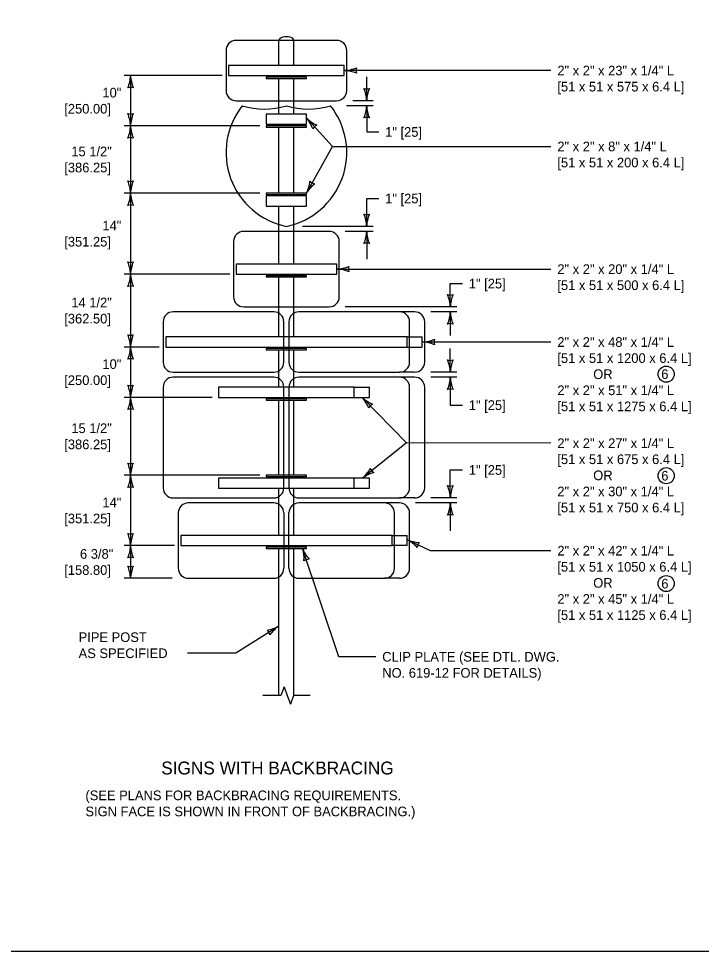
# Model space of a CAD drawing. Extents: x 49991.4 to 50021, y 49987.6 to 50011.4.
# Drawn here: x 50002.88 to 50007.12, y 49987.8 to 49993.6 of the extents above; entities that cross this region are included whole.
import ezdxf

# ---------------------------------------------------------------- set-up
doc = ezdxf.new("R2010")
doc.units = 0
for name, color, linetype in [('Level 1', 7, 'Continuous'), ('Level 2', 7, 'Continuous'), ('Level 3', 7, 'Continuous'), ('Level 4', 7, 'Continuous'), ('Level 6', 7, 'Continuous')]:
    doc.layers.add(name, color=color, linetype=linetype)

msp = doc.modelspace()

# ---------------------------------------------------------------- linework, layer by layer
at = {"layer": 'Level 1'}
for p, q in [((50004.4975, 49993.3041), (50004.4975, 49993.4604)), ((50004.5913, 49993.3041), (50004.5913, 49993.4604)), ((50004.4975, 49993.0013), (50004.4975, 49993.2241)), ((50004.5913, 49993.0013), (50004.5913, 49993.2241)), ((50004.4975, 49992.5108), (50004.4975, 49992.9213)), ((50004.5913, 49992.5108), (50004.5913, 49992.9213)), ((50004.4975, 49992.07), (50004.4975, 49992.4308)), ((50004.5913, 49992.07), (50004.5913, 49992.4308)), ((50004.4975, 49991.617), (50004.4975, 49991.99)), ((50004.5913, 49991.617), (50004.5913, 49991.99)), ((50005.2948, 49991.617), (50003.7948, 49991.617)), ((50003.7948, 49991.617), (50003.7948, 49991.5545)), ((50005.2948, 49991.5545), (50005.2948, 49991.617)), ((50003.7948, 49991.5545), (50005.2948, 49991.5545)), ((50004.4975, 49991.3041), (50004.4975, 49991.537)), ((50004.5132, 49991.5545), (50004.6292, 49991.5545)), ((50004.5913, 49991.3041), (50004.5913, 49991.537)), ((50004.9667, 49991.3041), (50004.1229, 49991.3041)), ((50004.1229, 49991.3041), (50004.1229, 49991.2416)), ((50004.9667, 49991.2416), (50004.9667, 49991.3041)), ((50004.1229, 49991.2416), (50004.9667, 49991.2416)), ((50004.4975, 49990.7576), (50004.4975, 49991.2241)), ((50004.5913, 49990.7576), (50004.5913, 49991.2241)), ((50004.9667, 49990.7401), (50004.1229, 49990.7401)), ((50004.1229, 49990.7401), (50004.1229, 49990.6776)), ((50004.9667, 49990.6776), (50004.9667, 49990.7401)), ((50004.1229, 49990.6776), (50004.9667, 49990.6776)), ((50004.4975, 49990.3826), (50004.4975, 49990.6776)), ((50004.5913, 49990.3826), (50004.5913, 49990.6776)), ((50005.2011, 49990.3826), (50003.8886, 49990.3826)), ((50003.8886, 49990.3826), (50003.8886, 49990.3201)), ((50005.2011, 49990.3201), (50005.2011, 49990.3826)), ((50003.8886, 49990.3201), (50005.2011, 49990.3201)), ((50004.4975, 49989.3888), (50004.4975, 49990.3026)), ((50004.5913, 49989.3888), (50004.5913, 49990.3026))]:
    msp.add_line(p, q, dxfattribs=at)
for points in [[(49999.3835, 49998.9992), (50016.7501, 49998.9992), (50016.7501, 49987.7988), (49999.3835, 49987.7988)], [(50004.1851, 49993.2416), (50004.9038, 49993.2416), (50004.9038, 49993.3041), (50004.1851, 49993.3041)], [(50004.4194, 49993.2241), (50004.6694, 49993.2241), (50004.6694, 49993.2319), (50004.4194, 49993.2319)], [(50004.4198, 49992.9388), (50004.6698, 49992.9388), (50004.6698, 49993.0013), (50004.4198, 49993.0013)], [(50004.4198, 49992.9213), (50004.6698, 49992.9213), (50004.6698, 49992.9291), (50004.4198, 49992.9291)], [(50004.4198, 49992.503), (50004.6698, 49992.503), (50004.6698, 49992.5108), (50004.4198, 49992.5108)], [(50004.4198, 49992.4308), (50004.6698, 49992.4308), (50004.6698, 49992.4933), (50004.4198, 49992.4933)], [(50004.2323, 49992.0075), (50004.8573, 49992.0075), (50004.8573, 49992.07), (50004.2323, 49992.07)], [(50004.4198, 49991.99), (50004.6698, 49991.99), (50004.6698, 49991.9978), (50004.4198, 49991.9978)], [(50004.4198, 49991.537), (50004.6698, 49991.537), (50004.6698, 49991.5448), (50004.4198, 49991.5448)], [(50004.4198, 49991.2241), (50004.6698, 49991.2241), (50004.6698, 49991.2319), (50004.4198, 49991.2319)], [(50004.4198, 49990.7498), (50004.6698, 49990.7498), (50004.6698, 49990.7576), (50004.4198, 49990.7576)], [(50004.4198, 49990.3026), (50004.6698, 49990.3026), (50004.6698, 49990.3104), (50004.4198, 49990.3104)]]:
    msp.add_lwpolyline(points, close=True, dxfattribs=at)
msp.add_ellipse((50004.5444, 49993.4604), major_axis=(0.0469, 0), ratio=0.488273, start_param=0, end_param=3.141593, dxfattribs=at)
at = {"layer": 'Level 2'}
for centre in [(50006.9044, 49991.386), (50006.9044, 49990.7548), (50006.9044, 49990.0842)]:
    msp.add_circle(centre, 0.05, dxfattribs=at)
at = {"layer": 'Level 3'}
for p, q in [((50006.1882, 49993.2729), (50004.9038, 49993.2729)), ((50004.1451, 49993.2416), (50003.5361, 49993.2416)), ((50003.5761, 49993.2416), (50003.5761, 49992.9291)), ((50005.0434, 49993.0854), (50005.0434, 49993.2329)), ((50005.0834, 49993.0854), (50004.9569, 49993.0854)), ((50005.0834, 49993.0543), (50004.9184, 49993.0543)), ((50005.0434, 49993.0542), (50005.0434, 49992.8911)), ((50004.6698, 49992.9782), (50004.8302, 49992.8011)), ((50004.3798, 49992.9291), (50003.5361, 49992.9291)), ((50003.5761, 49992.9291), (50003.5761, 49992.5108)), ((50005.0434, 49992.8911), (50005.1184, 49992.8911)), ((50004.6689, 49992.5108), (50004.8302, 49992.8011)), ((50004.8302, 49992.8011), (50006.1882, 49992.8011)), ((50004.3798, 49992.5108), (50003.5361, 49992.5108)), ((50003.5761, 49992.5108), (50003.5761, 49992.0075)), ((50005.0434, 49992.3043), (50005.0434, 49992.4778)), ((50005.0434, 49992.4778), (50005.1184, 49992.4778)), ((50005.0834, 49992.3043), (50004.6447, 49992.3043)), ((50005.0834, 49992.2731), (50004.9104, 49992.2731)), ((50005.0434, 49992.2731), (50005.0434, 49992.0997)), ((50004.8573, 49992.0387), (50006.1882, 49992.0387)), ((50004.1923, 49992.0075), (50003.5361, 49992.0075)), ((50003.5761, 49992.0075), (50003.5761, 49991.5545)), ((50005.563, 49991.8044), (50005.563, 49991.9487)), ((50005.563, 49991.9487), (50005.638, 49991.9487)), ((50005.603, 49991.8044), (50004.9104, 49991.8044)), ((50005.603, 49991.7732), (50005.4414, 49991.7732)), ((50005.563, 49991.7732), (50005.563, 49991.6257)), ((50006.1882, 49991.5857), (50005.3886, 49991.5857)), ((50003.7548, 49991.5545), (50003.5361, 49991.5545)), ((50003.5761, 49991.5545), (50003.5761, 49991.2416)), ((50005.563, 49991.3982), (50005.563, 49991.5457)), ((50005.603, 49991.3982), (50005.4414, 49991.3982)), ((50005.603, 49991.367), (50005.4414, 49991.367)), ((50005.563, 49991.367), (50005.563, 49991.1936)), ((50004.0829, 49991.2416), (50003.5361, 49991.2416)), ((50003.5761, 49991.2416), (50003.5761, 49990.7576)), ((50005.2913, 49990.9584), (50005.0148, 49991.2416)), ((50005.563, 49991.1936), (50005.638, 49991.1936)), ((50005.2913, 49990.9584), (50005.0171, 49990.7401)), ((50006.1882, 49990.957), (50005.2913, 49990.9584)), ((50004.3798, 49990.7576), (50003.5361, 49990.7576)), ((50003.5761, 49990.7576), (50003.5761, 49990.3201)), ((50005.563, 49990.617), (50005.563, 49990.7904)), ((50005.563, 49990.7904), (50005.638, 49990.7904)), ((50005.603, 49990.5858), (50005.3477, 49990.5858)), ((50005.603, 49990.617), (50005.4414, 49990.617)), ((50005.563, 49990.5858), (50005.563, 49990.4124)), ((50005.4405, 49990.2888), (50005.2949, 49990.3569)), ((50003.8486, 49990.3201), (50003.5361, 49990.3201)), ((50003.5761, 49990.3201), (50003.5761, 49990.1171)), ((50004.8705, 49989.6295), (50004.6456, 49990.3026)), ((50006.1882, 49990.2888), (50005.4405, 49990.2888)), ((50003.835, 49990.1171), (50003.5361, 49990.1171)), ((50004.4975, 49989.8207), (50004.2295, 49989.6513)), ((50004.2295, 49989.6513), (50003.9308, 49989.6513)), ((50005.1002, 49989.6295), (50004.8705, 49989.6295))]:
    msp.add_line(p, q, dxfattribs=at)
for centre, radius, start, end in [((50004.8923, 49993.5056), 0.233, 272.82731, 292.07716), ((50004.8946, 49993.0508), 0.2223, 67.45601, 87.63952), ((50005.032, 49993.2729), 0.0548, 162.13882, 197.86118), ((50003.354, 49993.2508), 0.2223, 337.45601, 357.63952), ((50003.8088, 49993.2531), 0.233, 182.82731, 202.07716), ((50003.5761, 49993.1134), 0.0548, 72.13882, 107.86118), ((50005.0434, 49993.2136), 0.0548, 252.13882, 287.86118), ((50004.8107, 49993.0739), 0.233, 2.82731, 22.07716), ((50005.2655, 49993.0763), 0.2223, 157.45601, 177.63952), ((50004.8213, 49993.0635), 0.2223, 337.45601, 357.63952), ((50005.2761, 49993.0658), 0.233, 182.82731, 202.07716), ((50003.5761, 49993.0573), 0.0548, 252.13882, 287.86118), ((50003.3434, 49992.9176), 0.233, 2.82731, 22.07716), ((50003.7982, 49992.92), 0.2223, 157.45601, 177.63952), ((50004.499, 49992.8358), 0.2223, 19.62889, 39.81239), ((50004.8346, 49993.1429), 0.233, 225.00019, 244.25004), ((50005.0434, 49992.9261), 0.0548, 72.13882, 107.86118), ((50003.354, 49992.9383), 0.2223, 337.45601, 357.63952), ((50003.8088, 49992.9406), 0.233, 182.82731, 202.07716), ((50004.7559, 49992.8832), 0.0548, 114.31169, 150.03406), ((50003.5761, 49992.8009), 0.0548, 72.13882, 107.86118), ((50003.5761, 49992.639), 0.0548, 252.13882, 287.86118), ((50003.3434, 49992.4993), 0.233, 2.82731, 22.07716), ((50003.7982, 49992.5017), 0.2223, 157.45601, 177.63952), ((50004.4599, 49992.6138), 0.233, 333.76259, 353.01244), ((50004.8586, 49992.3949), 0.2223, 128.39129, 148.5748), ((50004.7311, 49992.6229), 0.0548, 223.0741, 258.79646), ((50003.354, 49992.52), 0.2223, 337.45601, 357.63952), ((50003.8088, 49992.5223), 0.233, 182.82731, 202.07716), ((50003.5761, 49992.3826), 0.0548, 72.13882, 107.86118), ((50005.0434, 49992.4325), 0.0548, 252.13882, 287.86118), ((50004.8107, 49992.2928), 0.233, 2.82731, 22.07716), ((50005.2655, 49992.2952), 0.2223, 157.45601, 177.63952), ((50004.8213, 49992.2823), 0.2223, 337.45601, 357.63952), ((50005.2761, 49992.2846), 0.233, 182.82731, 202.07716), ((50005.0434, 49992.1449), 0.0548, 72.13882, 107.86118), ((50003.5761, 49992.1357), 0.0548, 252.13882, 287.86118), ((50003.3434, 49991.996), 0.233, 2.82731, 22.07716), ((50003.7982, 49991.9984), 0.2223, 157.45601, 177.63952), ((50004.8458, 49992.2714), 0.233, 272.82731, 292.07716), ((50004.8481, 49991.8166), 0.2223, 67.45601, 87.63952), ((50004.9855, 49992.0387), 0.0548, 162.13882, 197.86118), ((50003.354, 49992.0167), 0.2223, 337.45601, 357.63952), ((50003.8088, 49992.019), 0.233, 182.82731, 202.07716), ((50003.5761, 49991.8793), 0.0548, 72.13882, 107.86118), ((50005.563, 49991.9326), 0.0548, 252.13882, 287.86118), ((50005.3303, 49991.7929), 0.233, 2.82731, 22.07716), ((50005.7851, 49991.7953), 0.2223, 157.45601, 177.63952), ((50005.3409, 49991.7824), 0.2223, 337.45601, 357.63952), ((50005.7957, 49991.7847), 0.233, 182.82731, 202.07716), ((50005.563, 49991.645), 0.0548, 72.13882, 107.86118), ((50003.5761, 49991.6827), 0.0548, 252.13882, 287.86118), ((50003.3434, 49991.543), 0.233, 2.82731, 22.07716), ((50003.7982, 49991.5454), 0.2223, 157.45601, 177.63952), ((50005.3771, 49991.8184), 0.233, 272.82731, 292.07716), ((50005.3794, 49991.3636), 0.2223, 67.45601, 87.63952), ((50005.5168, 49991.5857), 0.0548, 162.13882, 197.86118), ((50003.354, 49991.5637), 0.2223, 337.45601, 357.63952), ((50003.8088, 49991.566), 0.233, 182.82731, 202.07716), ((50003.5761, 49991.4263), 0.0548, 72.13882, 107.86118), ((50005.563, 49991.5264), 0.0548, 252.13882, 287.86118), ((50005.3303, 49991.3867), 0.233, 2.82731, 22.07716), ((50005.7851, 49991.3891), 0.2223, 157.45601, 177.63952), ((50005.3409, 49991.3762), 0.2223, 337.45601, 357.63952), ((50005.7957, 49991.3785), 0.233, 182.82731, 202.07716), ((50003.5761, 49991.3698), 0.0548, 252.13882, 287.86118), ((50003.3434, 49991.2301), 0.233, 2.82731, 22.07716), ((50003.7982, 49991.2325), 0.2223, 157.45601, 177.63952), ((50005.563, 49991.2388), 0.0548, 72.13882, 107.86118), ((50003.354, 49991.2508), 0.2223, 337.45601, 357.63952), ((50003.8088, 49991.2531), 0.233, 182.82731, 202.07716), ((50004.8495, 49991.093), 0.2223, 21.76807, 41.95157), ((50005.1733, 49991.4124), 0.233, 227.13937, 246.38922), ((50003.5761, 49991.1134), 0.0548, 72.13882, 107.86118), ((50005.1044, 49991.1499), 0.0548, 116.45087, 152.17324), ((50003.5761, 49990.8858), 0.0548, 252.13882, 287.86118), ((50003.3434, 49990.7461), 0.233, 2.82731, 22.07716), ((50003.7982, 49990.7485), 0.2223, 157.45601, 177.63952), ((50003.354, 49990.7668), 0.2223, 337.45601, 357.63952), ((50003.8088, 49990.7691), 0.233, 182.82731, 202.07716), ((50004.8632, 49990.915), 0.233, 311.35066, 330.60051), ((50005.1483, 49990.5606), 0.2223, 105.97936, 126.16287), ((50005.1174, 49990.82), 0.0548, 200.66217, 236.38453), ((50003.5761, 49990.6294), 0.0548, 72.13882, 107.86118), ((50005.563, 49990.7452), 0.0548, 252.13882, 287.86118), ((50005.3303, 49990.6055), 0.233, 2.82731, 22.07716), ((50005.7851, 49990.6079), 0.2223, 157.45601, 177.63952), ((50005.3409, 49990.595), 0.2223, 337.45601, 357.63952), ((50005.7957, 49990.5973), 0.233, 182.82731, 202.07716), ((50005.563, 49990.4576), 0.0548, 72.13882, 107.86118), ((50003.5761, 49990.4483), 0.0548, 252.13882, 287.86118), ((50003.3434, 49990.3086), 0.233, 2.82731, 22.07716), ((50003.7982, 49990.311), 0.2223, 157.45601, 177.63952), ((50005.1925, 49990.1596), 0.2223, 42.38855, 62.57206), ((50005.3831, 49990.5726), 0.233, 247.75985, 267.0097), ((50003.354, 49990.3293), 0.2223, 337.45601, 357.63952), ((50003.8088, 49990.3316), 0.233, 182.82731, 202.07716), ((50004.432, 49990.2409), 0.2223, 355.93304, 16.11655), ((50004.8627, 49990.3873), 0.233, 201.30434, 220.55419), ((50005.411, 49990.3026), 0.0548, 137.07136, 172.79372), ((50003.5761, 49990.1919), 0.0548, 72.13882, 107.86118), ((50004.6862, 49990.181), 0.0548, 90.61585, 126.33821), ((50003.5761, 49990.2453), 0.0548, 252.13882, 287.86118), ((50003.3434, 49990.1056), 0.233, 2.82731, 22.07716), ((50003.7982, 49990.108), 0.2223, 157.45601, 177.63952), ((50004.3866, 49990.0134), 0.2223, 279.75302, 299.93653), ((50004.3891, 49989.7522), 0.0548, 14.43583, 50.15819), ((50004.6316, 49989.6302), 0.233, 125.12432, 144.37417)]:
    msp.add_arc(centre, radius, start, end, dxfattribs=at)
at = {"layer": 'Level 4'}
for p, q in [((50004.8569, 49993.4604), (50004.2319, 49993.4604)), ((50004.1694, 49993.3979), (50004.1694, 49993.1479)), ((50004.9194, 49993.1479), (50004.9194, 49993.3979)), ((50004.2319, 49993.0854), (50004.8569, 49993.0854)), ((50004.8104, 49992.2731), (50004.2791, 49992.2731)), ((50004.2166, 49992.2106), (50004.2166, 49991.8669)), ((50004.8729, 49991.8669), (50004.8729, 49992.2106)), ((50004.2791, 49991.8044), (50004.8104, 49991.8044)), ((50004.4663, 49991.7732), (50003.8413, 49991.7732)), ((50005.2476, 49991.7732), (50004.6226, 49991.7732)), ((50005.3414, 49991.7732), (50005.2476, 49991.7732)), ((50003.7788, 49991.7107), (50003.7788, 49991.4607)), ((50004.5288, 49991.4607), (50004.5288, 49991.7107)), ((50004.5601, 49991.7107), (50004.5601, 49991.4607)), ((50005.3101, 49991.4607), (50005.3101, 49991.7107)), ((50005.4039, 49991.4607), (50005.4039, 49991.7107)), ((50005.2948, 49991.617), (50005.3886, 49991.617)), ((50005.3886, 49991.5545), (50005.3886, 49991.617)), ((50005.2948, 49991.5545), (50005.3886, 49991.5545)), ((50003.8413, 49991.3982), (50004.4663, 49991.3982)), ((50004.6226, 49991.3982), (50005.2476, 49991.3982)), ((50005.3414, 49991.3982), (50005.2476, 49991.3982)), ((50004.4663, 49991.367), (50003.8413, 49991.367)), ((50005.2476, 49991.367), (50004.6226, 49991.367)), ((50005.3414, 49991.367), (50005.2476, 49991.367)), ((50003.7788, 49991.3045), (50003.7788, 49990.6795)), ((50004.5288, 49990.6795), (50004.5288, 49991.3045)), ((50004.5601, 49991.3045), (50004.5601, 49990.6795)), ((50004.9667, 49991.3041), (50005.0605, 49991.3041)), ((50005.0605, 49991.2416), (50005.0605, 49991.3041)), ((50005.3101, 49990.6795), (50005.3101, 49991.3045)), ((50005.4039, 49990.6795), (50005.4039, 49991.3045)), ((50004.9667, 49991.2416), (50005.0605, 49991.2416)), ((50005.0605, 49990.7401), (50004.9667, 49990.7401)), ((50005.0605, 49990.6776), (50005.0605, 49990.7401)), ((50004.9667, 49990.6776), (50005.0605, 49990.6776)), ((50003.8413, 49990.617), (50004.4663, 49990.617)), ((50004.4663, 49990.5858), (50003.935, 49990.5858)), ((50004.6226, 49990.617), (50005.2476, 49990.617)), ((50005.1539, 49990.5858), (50004.6226, 49990.5858)), ((50005.2477, 49990.5858), (50005.1539, 49990.5858)), ((50005.3414, 49990.617), (50005.2476, 49990.617)), ((50003.8725, 49990.5233), (50003.8725, 49990.1796)), ((50004.5288, 49990.5233), (50004.5288, 49990.1796)), ((50004.5601, 49990.1796), (50004.5601, 49990.5233)), ((50005.2164, 49990.1796), (50005.2164, 49990.5233)), ((50005.3102, 49990.1796), (50005.3102, 49990.5233)), ((50005.2011, 49990.3826), (50005.2949, 49990.3826)), ((50005.2949, 49990.3201), (50005.2949, 49990.3826)), ((50005.2949, 49990.3201), (50005.2011, 49990.3201)), ((50003.935, 49990.1171), (50004.4663, 49990.1171)), ((50004.6226, 49990.1171), (50005.1539, 49990.1171)), ((50005.2477, 49990.1171), (50005.1539, 49990.1171))]:
    msp.add_line(p, q, dxfattribs=at)
for centre, radius, start, end in [((50004.2319, 49993.3979), 0.0625, 90, 180), ((50004.8569, 49993.3979), 0.0625, 0, 90), ((50004.2319, 49993.1479), 0.0625, 180, 270), ((50004.8569, 49993.1479), 0.0625, 270, 0), ((50004.638, 49992.7635), 0.4686, 141.64747, 258.51488), ((50004.4074, 49993.503), 0.4692, 253.02958, 286.97042), ((50004.6813, 49993.503), 0.4692, 253.02958, 286.98194), ((50004.4506, 49992.7636), 0.4688, 281.57863, 38.3229), ((50004.2791, 49992.2106), 0.0625, 90, 180), ((50004.8104, 49992.2106), 0.0625, 0, 90), ((50004.2791, 49991.8669), 0.0625, 180, 270), ((50004.8104, 49991.8669), 0.0625, 270, 0), ((50003.8413, 49991.7107), 0.0625, 90, 180), ((50004.4663, 49991.7107), 0.0625, 0, 90), ((50004.6226, 49991.7107), 0.0625, 90, 180), ((50005.2476, 49991.7107), 0.0625, 0, 90), ((50005.3414, 49991.7107), 0.0625, 0, 90), ((50003.8413, 49991.4607), 0.0625, 180, 270), ((50004.4663, 49991.4607), 0.0625, 270, 0), ((50004.6226, 49991.4607), 0.0625, 180, 270), ((50005.2476, 49991.4607), 0.0625, 270, 0), ((50005.3414, 49991.4607), 0.0625, 270, 0), ((50003.8413, 49991.3045), 0.0625, 90, 180), ((50004.4663, 49991.3045), 0.0625, 0, 90), ((50004.6226, 49991.3045), 0.0625, 90, 180), ((50005.2476, 49991.3045), 0.0625, 0, 90), ((50005.3414, 49991.3045), 0.0625, 0, 90), ((50003.8413, 49990.6795), 0.0625, 180, 270), ((50004.4663, 49990.6795), 0.0625, 270, 0), ((50004.6226, 49990.6795), 0.0625, 180, 270), ((50005.2476, 49990.6795), 0.0625, 270, 0), ((50005.3414, 49990.6795), 0.0625, 270, 0), ((50003.935, 49990.5233), 0.0625, 90, 180), ((50004.4663, 49990.5233), 0.0625, 0, 90), ((50004.6226, 49990.5233), 0.0625, 90, 180), ((50005.1539, 49990.5233), 0.0625, 0, 90), ((50005.2477, 49990.5233), 0.0625, 0, 90), ((50003.935, 49990.1796), 0.0625, 180, 270), ((50004.4663, 49990.1796), 0.0625, 270, 0), ((50004.6226, 49990.1796), 0.0625, 180, 270), ((50005.1539, 49990.1796), 0.0625, 270, 0), ((50005.2477, 49990.1796), 0.0625, 270, 0)]:
    msp.add_arc(centre, radius, start, end, dxfattribs=at)
at = {"layer": 'Level 6'}
for p, q in [((50004.5303, 49989.4436), (50004.5108, 49989.3888)), ((50004.5303, 49989.4436), (50004.5497, 49989.3888)), ((50004.5108, 49989.3888), (50004.3975, 49989.3888)), ((50004.5497, 49989.3888), (50004.5691, 49989.334)), ((50004.5886, 49989.3888), (50004.5691, 49989.334)), ((50004.6913, 49989.3888), (50004.5886, 49989.3888))]:
    msp.add_line(p, q, dxfattribs=at)

# ---------------------------------------------------------------- texts
at = {"layer": 'Level 2'}
for s, height, p in [('2" x 2" x 23" x 1/4" L', 0.06, (50006.2282, 49993.2429)), ('[51 x 51 x 575 x 6.4 L]', 0.06, (50006.2282, 49993.1429)), ('10"', 0.06, (50003.4015, 49993.1054)), ('[250.00]', 0.06, (50003.1643, 49993.0054)), ('1" [25]', 0.06, (50005.1584, 49992.8611)), ('15 1/2"', 0.06, (50003.2081, 49992.74)), ('2" x 2" x 8" x 1/4" L', 0.06, (50006.2282, 49992.7711)), ('[51 x 51 x 200 x 6.4 L]', 0.06, (50006.2282, 49992.6711)), ('[386.25]', 0.06, (50003.1643, 49992.64)), ('1" [25]', 0.06, (50005.1584, 49992.4478)), ('14"', 0.06, (50003.4015, 49992.2792)), ('[351.25]', 0.06, (50003.1643, 49992.1792)), ('2" x 2" x 20" x 1/4" L', 0.06, (50006.2282, 49992.0087)), ('1" [25]', 0.06, (50005.678, 49991.9187)), ('[51 x 51 x 500 x 6.4 L]', 0.06, (50006.2282, 49991.9087)), ('14 1/2"', 0.06, (50003.2081, 49991.801)), ('[362.50]', 0.06, (50003.1643, 49991.701)), ('2" x 2" x 48" x 1/4" L', 0.06, (50006.2282, 49991.5557)), ('[51 x 51 x 1200 x 6.4 L]', 0.06, (50006.2282, 49991.4557)), ('10"', 0.06, (50003.4015, 49991.4183)), ('          OR', 0.06, (50006.2282, 49991.3557)), ('6', 0.06, (50006.874, 49991.356)), ('[250.00]', 0.06, (50003.1643, 49991.3183)), ('2" x 2" x 51" x 1/4" L', 0.06, (50006.2282, 49991.2557)), ('1" [25]', 0.06, (50005.678, 49991.1636)), ('[51 x 51 x 1275 x 6.4 L]', 0.06, (50006.2282, 49991.1557)), ('15 1/2"', 0.06, (50003.2081, 49991.0196)), ('2" x 2" x 27" x 1/4" L', 0.06, (50006.2282, 49990.927)), ('[386.25]', 0.06, (50003.1643, 49990.9196)), ('[51 x 51 x 675 x 6.4 L]', 0.06, (50006.2282, 49990.827)), ('1" [25]', 0.06, (50005.678, 49990.7604)), ('          OR', 0.06, (50006.2282, 49990.727)), ('6', 0.06, (50006.874, 49990.7248)), ('2" x 2" x 30" x 1/4" L', 0.06, (50006.2282, 49990.627)), ('14"', 0.06, (50003.4015, 49990.5589)), ('[51 x 51 x 750 x 6.4 L]', 0.06, (50006.2282, 49990.527)), ('[351.25]', 0.06, (50003.1643, 49990.4589)), ('6 3/8"', 0.06, (50003.262, 49990.2386)), ('2" x 2" x 42" x 1/4" L', 0.06, (50006.2282, 49990.2588)), ('[158.80]', 0.06, (50003.1643, 49990.1386)), ('[51 x 51 x 1050 x 6.4 L]', 0.06, (50006.2282, 49990.1588)), ('          OR', 0.06, (50006.2282, 49990.0588)), ('6', 0.06, (50006.874, 49990.0542)), ('2" x 2" x 45" x 1/4" L', 0.06, (50006.2282, 49989.9588)), ('[51 x 51 x 1125 x 6.4 L]', 0.06, (50006.2282, 49989.8588)), ('PIPE POST', 0.06, (50003.2535, 49989.7213)), ('AS SPECIFIED', 0.06, (50003.2535, 49989.6213)), ('CLIP PLATE (SEE DTL. DWG.', 0.06, (50005.1402, 49989.5995)), ('NO. 619-12 FOR DETAILS)', 0.06, (50005.1402, 49989.4995)), ('SIGNS WITH BACKBRACING', 0.08, (50003.7668, 49988.8982)), ('(SEE PLANS FOR BACKBRACING REQUIREMENTS.', 0.06, (50003.2957, 49988.7382)), ('SIGN FACE IS SHOWN IN FRONT OF BACKBRACING.)', 0.06, (50003.2957, 49988.6382))]:
    msp.add_text(s, height=height, dxfattribs=at).set_placement(p)

doc.saveas('drawing.dxf')
